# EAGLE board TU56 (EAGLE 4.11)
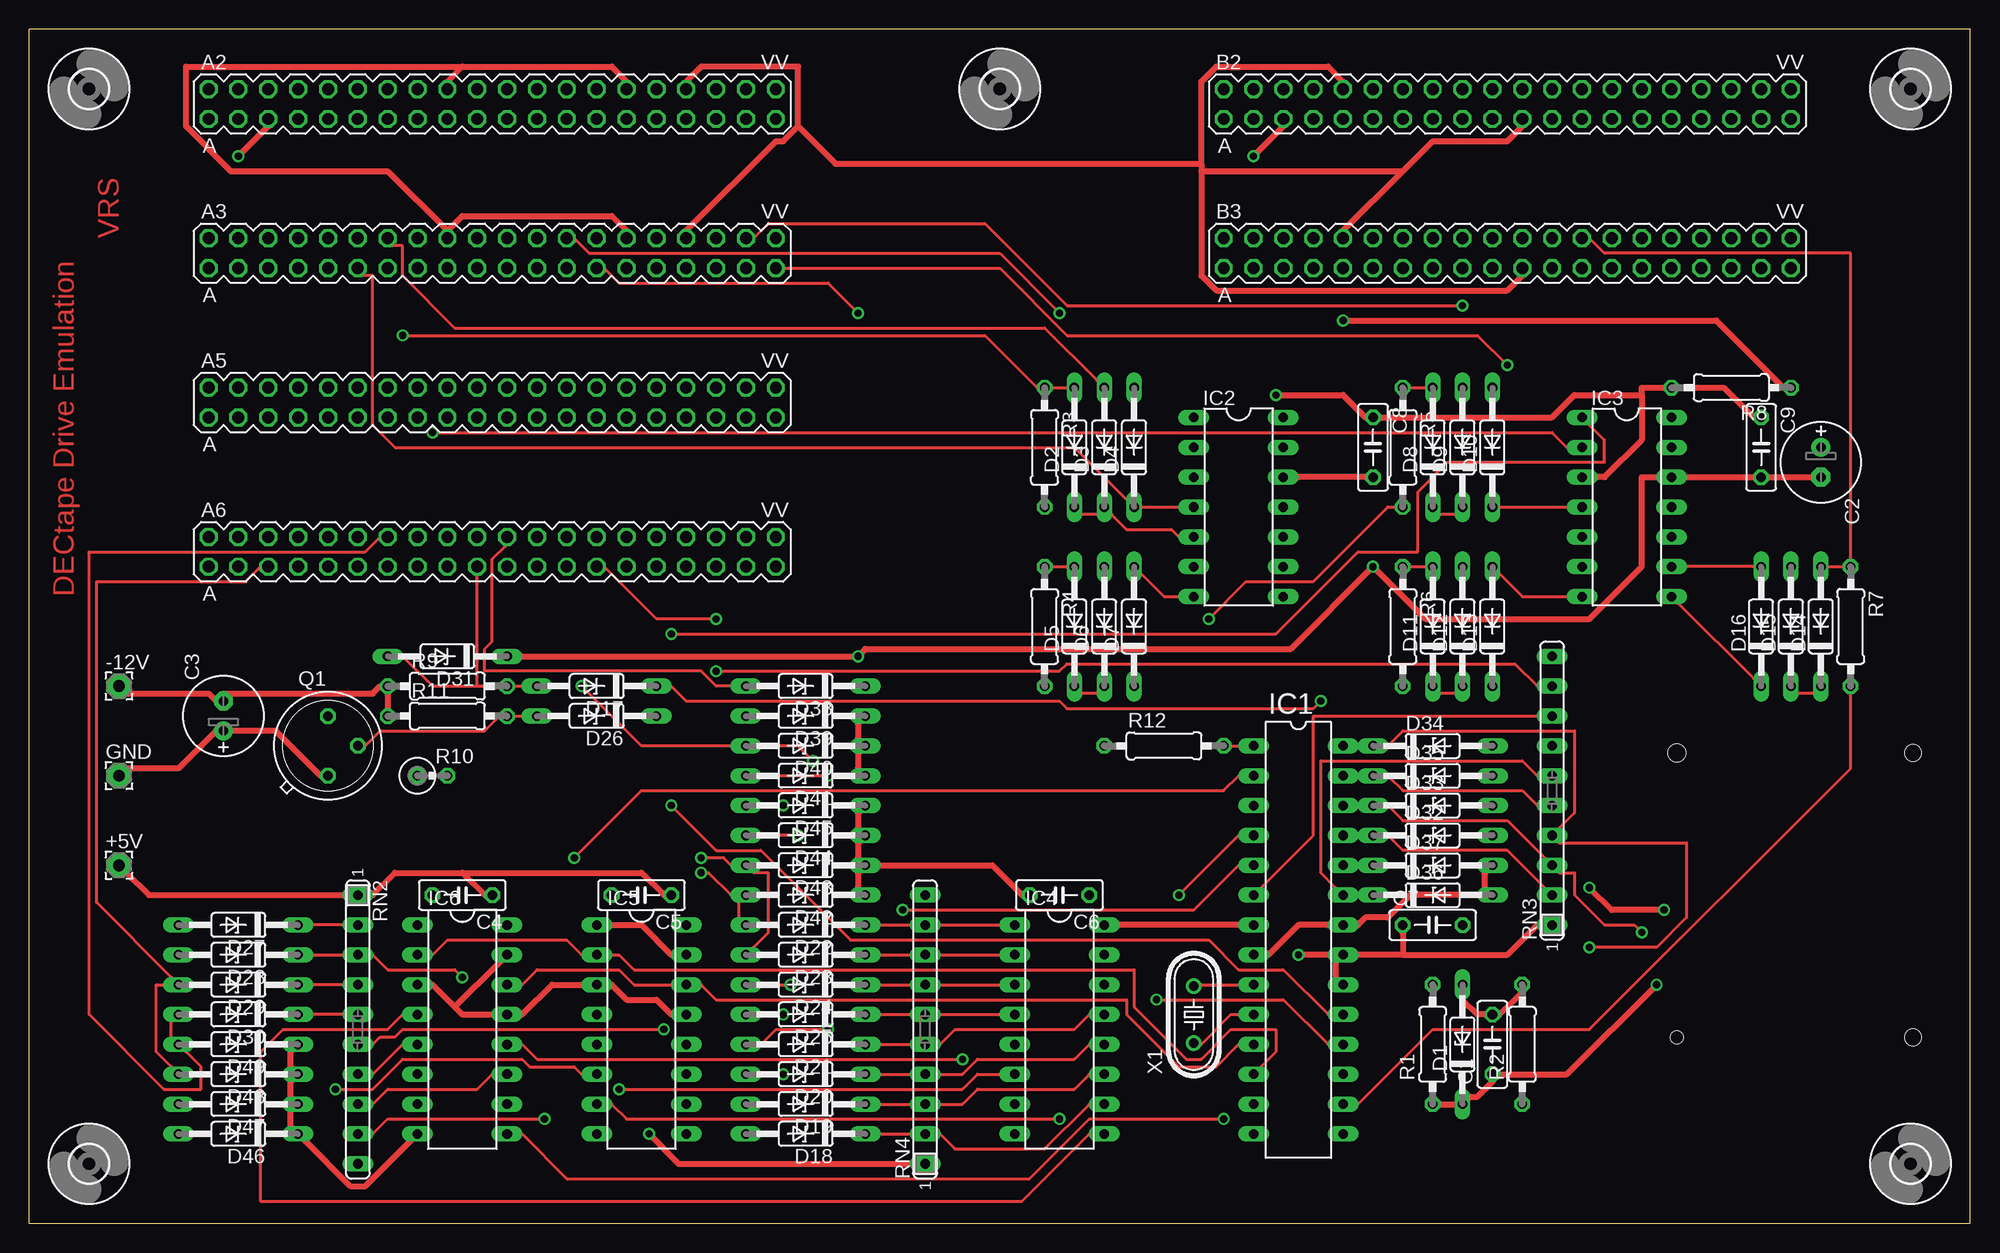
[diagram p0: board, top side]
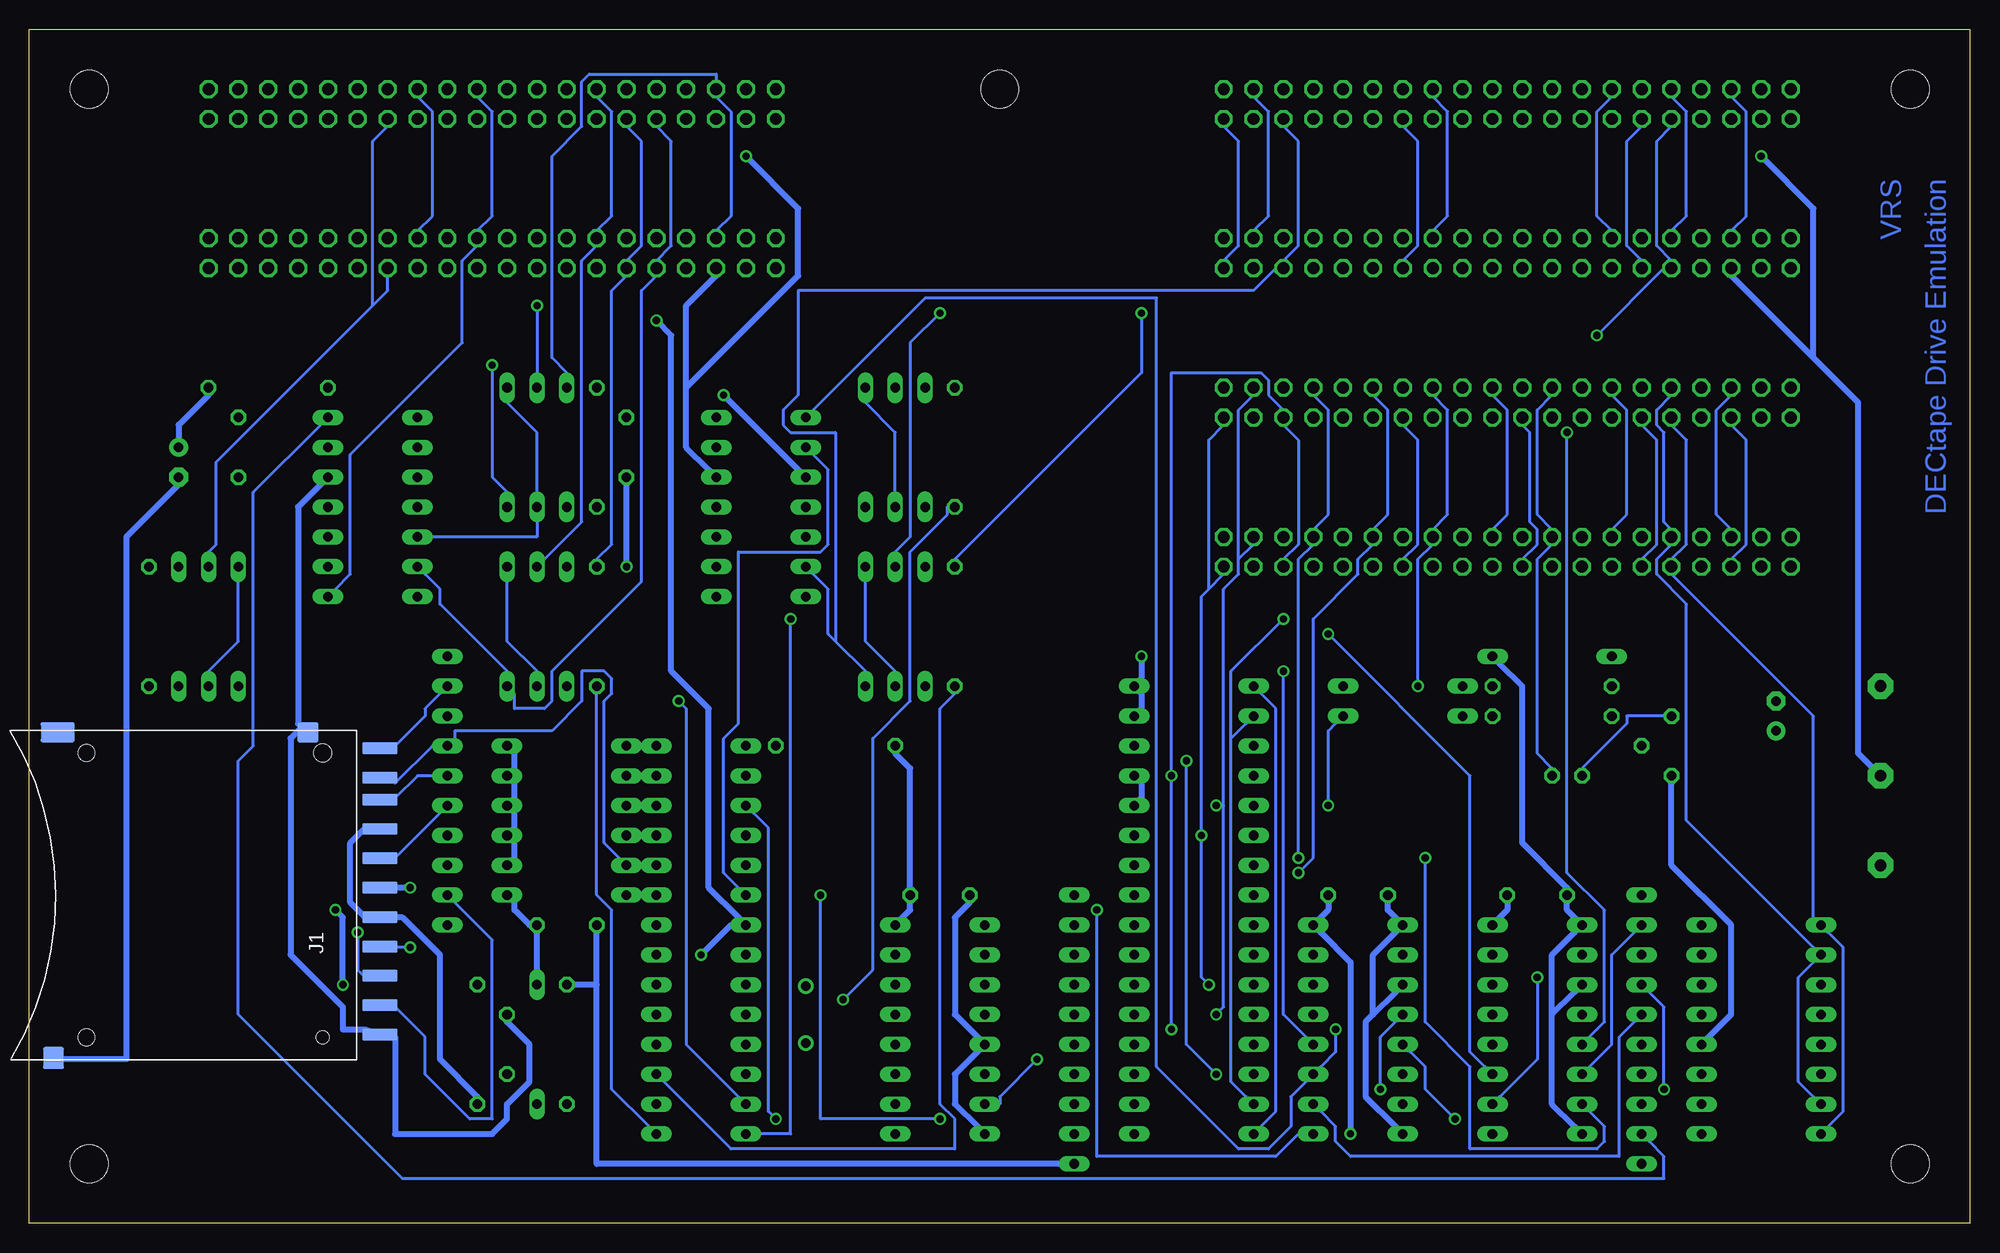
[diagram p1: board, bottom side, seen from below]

Size 165.1 x 101.6 mm. Coordinates in mm from the lower left corner, seen from the top.
Outline: 0,0 165.1,0 165.1,101.6 0,101.6 0,0
Copper layers (1*16): Top 0.035mm / dielectric 1.5mm / Bottom 0.035mm
Design rules "custompcb": minimum track width 10mil, minimum drill 24mil, track to track 8mil, track to pad 8mil, pad to pad 8mil, via to via 8mil, smd to smd 0mil, copper to edge 10mil, drill to drill 8mil, minimum pad ring 10mil, minimum via ring 8mil, stop-mask expansion 4mil, vias tented up to drill 0mil, thermal gap 10mil
Net classes: 1 Supply: width 0.508 mm, drill 0.381 mm

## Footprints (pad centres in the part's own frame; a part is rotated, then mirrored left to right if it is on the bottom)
2,15/1,0 = drill 1.016 pad 2.159 octagon: 1 0,0
DEC40PINV = drill 1.016 octagon: A -24.13,-1.27; AA 3.81,-1.27; B -24.13,1.27; BB 3.81,1.27; C -21.59,-1.27; CC 6.35,-1.27; D -21.59,1.27; DD 6.35,1.27; E -19.05,-1.27; EE 8.89,-1.27; F -19.05,1.27; FF 8.89,1.27; H -16.51,-1.27; HH 11.43,-1.27; J -16.51,1.27; JJ 11.43,1.27; K -13.97,-1.27; KK 13.97,-1.27; L -13.97,1.27; LL 13.97,1.27; M -11.43,-1.27; MM 16.51,-1.27; N -11.43,1.27; NN 16.51,1.27; P -8.89,-1.27; PP 19.05,-1.27; R -8.89,1.27; RR 19.05,1.27; S -6.35,-1.27; SS 21.59,-1.27; T -6.35,1.27; TT 21.59,1.27; U -3.81,-1.27; UU 24.13,-1.27; V -3.81,1.27; VV 24.13,1.27; W -1.27,-1.27; X -1.27,1.27; Y 1.27,-1.27; Z 1.27,1.27
C050-025X075 = drill 0.813 octagon: 1 -2.54,0; 2 2.54,0
E2,5-7 = drill 0.813 pad 1.6 round: + -1.27,0 | drill 0.813 pad 1.6 octagon: - 1.27,0
DO35Z10 = drill 0.813 long: A 5.08,0; C -5.08,0
DO35-10 = drill 0.813 long: A 5.08,0; C -5.08,0
DIL28-3 = drill 0.813 long: 1 -16.51,-3.81; 2 -13.97,-3.81; 3 -11.43,-3.81; 4 -8.89,-3.81; 5 -6.35,-3.81; 6 -3.81,-3.81; 7 -1.27,-3.81; 8 1.27,-3.81; 9 3.81,-3.81; 10 6.35,-3.81; 11 8.89,-3.81; 12 11.43,-3.81; 13 13.97,-3.81; 14 16.51,-3.81; 15 16.51,3.81; 16 13.97,3.81; 17 11.43,3.81; 18 8.89,3.81; 19 6.35,3.81; 20 3.81,3.81; 21 1.27,3.81; 22 -1.27,3.81; 23 -3.81,3.81; 24 -6.35,3.81; 25 -8.89,3.81; 26 -11.43,3.81; 27 -13.97,3.81; 28 -16.51,3.81
DIL14 = drill 0.813 long: 1 -7.62,-3.81; 2 -5.08,-3.81; 3 -2.54,-3.81; 4 0,-3.81; 5 2.54,-3.81; 6 5.08,-3.81; 7 7.62,-3.81; 8 7.62,3.81; 9 5.08,3.81; 10 2.54,3.81; 11 0,3.81; 12 -2.54,3.81; 13 -5.08,3.81; 14 -7.62,3.81
DIL16 = drill 0.813 long: 1 -8.89,-3.81; 2 -6.35,-3.81; 3 -3.81,-3.81; 4 -1.27,-3.81; 5 1.27,-3.81; 6 3.81,-3.81; 7 6.35,-3.81; 8 8.89,-3.81; 9 8.89,3.81; 10 6.35,3.81; 11 3.81,3.81; 12 1.27,3.81; 13 -1.27,3.81; 14 -3.81,3.81; 15 -6.35,3.81; 16 -8.89,3.81
SCDA1A = smd 1 x 2.95: 1 -6.865,-10.76; 2 -4.365,-10.76; 3 -1.865,-10.76; 4 0.635,-10.76; 5 3.135,-10.76; 6 5.635,-10.76; 7 8.135,-10.76; 8 10,-10.76; 9 -9.365,-10.76; 10 12.5,-10.76; 13 -11.865,-10.76 | smd 1.7 x 1.8: 11 13.85,-4.65 | smd 1.7 x 2.9: 12 13.85,16.65 | smd 1.9 x 1.8: 14 -13.85,17 | hole 1.05: -12.1,-5.9 | hole 1.5: 12.1,-5.9 | hole 1.4: 12.1,14.2; -12.1,14.2
TO5 = drill 0.813 octagon: 1 0,-2.54; 2 2.54,0; 3 0,2.54
0207/10 = drill 0.813 octagon: 1 -5.08,0; 2 5.08,0
0309V = drill 0.813 octagon: 1 -1.27,0; 2 1.27,0
SIL10 = drill 0.813 long: 1 -11.43,0; 2 -8.89,0; 3 -6.35,0; 4 -3.81,0; 5 -1.27,0; 6 1.27,0; 7 3.81,0; 8 6.35,0; 9 8.89,0; 10 11.43,0
3,2 = hole 3.2: 0,0
HC49/S = drill 0.813 round: 1 -2.413,0; 2 2.413,0

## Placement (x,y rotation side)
+5V  [2,15/1,0]  7.62,30.48 0 top
-12V  [2,15/1,0]  7.62,45.72 0 top
A2  [DEC40PINV]  39.37,95.25 0 top
A3  [DEC40PINV]  39.37,82.55 0 top
A5  [DEC40PINV]  39.37,69.85 0 top
A6  [DEC40PINV]  39.37,57.15 0 top
B2  [DEC40PINV]  125.73,95.25 0 top
B3  [DEC40PINV]  125.73,82.55 0 top
C1  .01  [C050-025X075]  124.46,15.24 90 top
C2  10uf  [E2,5-7]  152.4,64.77 270 top
C3  10uf  [E2,5-7]  16.51,43.18 90 top
C4  .01  [C050-025X075]  36.83,27.94 180 top
C5  .01  [C050-025X075]  52.07,27.94 180 top
C6  .01  [C050-025X075]  87.63,27.94 180 top
C7  .01  [C050-025X075]  119.38,25.4 0 top
C8  .01  [C050-025X075]  114.3,66.04 270 top
C9  .01  [C050-025X075]  147.32,66.04 270 top
D1  3.3V  [DO35Z10]  121.92,15.24 90 top
D2  1N4148  [DO35-10]  88.9,66.04 90 top
D3  1N4148  [DO35-10]  91.44,66.04 90 top
D4  1N4148  [DO35-10]  93.98,66.04 90 top
D5  1N4148  [DO35-10]  88.9,50.8 90 top
D6  1N4148  [DO35-10]  91.44,50.8 90 top
D7  1N4148  [DO35-10]  93.98,50.8 90 top
D8  1N4148  [DO35-10]  119.38,66.04 90 top
D9  1N4148  [DO35-10]  121.92,66.04 90 top
D10  1N4148  [DO35-10]  124.46,66.04 90 top
D11  1N4148  [DO35-10]  119.38,50.8 90 top
D12  1N4148  [DO35-10]  121.92,50.8 90 top
D13  1N4148  [DO35-10]  124.46,50.8 90 top
D14  1N4148  [DO35-10]  152.4,50.8 90 top
D15  1N4148  [DO35-10]  149.86,50.8 90 top
D16  1N4148  [DO35-10]  147.32,50.8 90 top
D17  3.3V  [DO35Z10]  48.26,45.72 180 top
D18  3.3V  [DO35Z10]  66.04,7.62 180 top
D19  3.3V  [DO35Z10]  66.04,10.16 180 top
D20  3.3V  [DO35Z10]  66.04,12.7 180 top
D21  3.3V  [DO35Z10]  66.04,15.24 180 top
D22  3.3V  [DO35Z10]  66.04,25.4 180 top
D23  3.3V  [DO35Z10]  66.04,22.86 180 top
D24  3.3V  [DO35Z10]  66.04,20.32 180 top
D25  3.3V  [DO35Z10]  66.04,17.78 180 top
D26  3.3V  [DO35Z10]  48.26,43.18 180 top
D27  3.3V  [DO35Z10]  17.78,25.4 180 top
D28  3.3V  [DO35Z10]  17.78,22.86 180 top
D29  3.3V  [DO35Z10]  17.78,20.32 180 top
D30  3.3V  [DO35Z10]  17.78,17.78 180 top
D31  3.3V  [DO35Z10]  35.56,48.26 180 top
D32  3.3V  [DO35Z10]  119.38,33.02 0 top
D33  3.3V  [DO35Z10]  119.38,35.56 0 top
D34  3.3V  [DO35Z10]  119.38,40.64 0 top
D35  3.3V  [DO35Z10]  119.38,38.1 0 top
D36  3.3V  [DO35Z10]  119.38,27.94 0 top
D37  3.3V  [DO35Z10]  119.38,30.48 0 top
D38  3.3V  [DO35Z10]  66.04,45.72 180 top
D39  3.3V  [DO35Z10]  66.04,43.18 180 top
D40  3.3V  [DO35Z10]  66.04,40.64 180 top
D41  3.3V  [DO35Z10]  66.04,38.1 180 top
D42  3.3V  [DO35Z10]  66.04,27.94 180 top
D43  3.3V  [DO35Z10]  66.04,30.48 180 top
D44  3.3V  [DO35Z10]  66.04,33.02 180 top
D45  3.3V  [DO35Z10]  66.04,35.56 180 top
D46  3.3V  [DO35Z10]  17.78,7.62 180 top
D47  3.3V  [DO35Z10]  17.78,10.16 180 top
D48  3.3V  [DO35Z10]  17.78,12.7 180 top
D49  3.3V  [DO35Z10]  17.78,15.24 180 top
GND  [2,15/1,0]  7.62,38.1 0 top
IC1  ATMEGA8L-8P  [DIL28-3]  107.95,24.13 270 top
IC2  LM339N  [DIL14]  102.87,60.96 270 top
IC3  LM339N  [DIL14]  135.89,60.96 270 top
IC4  74LS148N  [DIL16]  87.63,16.51 270 top
IC5  74LS153N  [DIL16]  52.07,16.51 270 top
IC6  74LS153N  [DIL16]  36.83,16.51 270 top
J1  SDCARDMOUSER  [SCDA1A]  146.05,27.94 90 bottom
Q1  2N2905  [TO5]  25.4,40.64 0 top
R1  [0207/10]  119.38,15.24 90 top
R2  0  [0207/10]  127,15.24 90 top
R3  10K  [0207/10]  86.36,66.04 270 top
R4  10K  [0207/10]  86.36,50.8 270 top
R5  10K  [0207/10]  116.84,66.04 270 top
R6  10K  [0207/10]  116.84,50.8 270 top
R7  10K  [0207/10]  154.94,50.8 270 top
R8  0  [0207/10]  144.78,71.12 180 top
R9  10K  [0207/10]  35.56,45.72 0 top
R10  100 1/2W  [0309V]  34.29,38.1 0 top
R11  10K  [0207/10]  35.56,43.18 0 top
R12  0  [0207/10]  96.52,40.64 0 top
RN2  [SIL10]  27.94,16.51 270 top
RN3  [SIL10]  129.54,36.83 90 top
RN4  [SIL10]  76.2,16.51 90 top
U$1  [3,2]  5.08,5.08 0 top
U$2  [3,2]  5.08,96.52 0 top
U$3  [3,2]  160.02,96.52 0 top
U$4  [3,2]  160.02,5.08 0 top
U$5  [3,2]  82.55,96.52 0 top
X1  [HC49/S]  99.06,17.78 90 top

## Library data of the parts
+5V -12V GND = wirepad
A2 A3 A5 A6 B2 B3 = dec-con
C1-C9 R1-R12 = rcl
D1-D49 = diode
IC1 = avr
IC2 IC3 = linear
IC4-IC6 = 74xx-jameco
J1 = sdcards
Q1 = transistor-pnp
RN2-RN4 = resistor-sil
U$1-U$5 = holes
X1 = crystal

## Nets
-12V [Supply]: -12V.1 C3.- R9.1 R11.1
A: IC1.11 IC5.14 IC6.14
B: IC1.12 IC5.2 IC6.2
CD\: IC5.12 J1.10 RN3.9
CLK: D35.C IC1.27 J1.5 RN3.5
CMD: D34.C IC1.28 J1.2 RN3.4
D0: IC1.5 IC5.9
D1: IC1.4 IC5.7
D1IN: IC3.14 IC5.5 RN2.9
D1OUT: IC1.16 R7.2
D2: IC1.3 IC6.9
D2IN: IC3.1 IC6.11 RN2.8
D2OUT: IC1.15 R6.2
D3: IC1.2 IC6.7
D3IN: IC3.2 IC6.5 RN2.7
D3OUT: IC1.14 R5.2
DAT0: D36.C IC1.23 J1.7 RN3.6
DAT1: D37.C IC1.24 J1.8 RN3.7
DAT2: D32.C IC1.25 J1.9 RN3.2
DAT3: D33.C IC1.26 J1.1 RN3.3
DATA1+: B2.DD B3.DD D14.A R7.1
DATA1-: B2.EE B3.EE D15.A
DATA1CT: B2.Z B3.Z D16.C IC3.8
DATA2+: B2.M B3.M D11.A R6.1
DATA2-: B2.R B3.R D12.A
DATA2CT: B2.K B3.K D13.C IC3.6
DATA3+: B2.F B3.F D8.A R5.1
DATA3-: A2.TT A3.TT D9.A
DATA3CT: A2.UU A3.UU D10.C IC3.4
DRV0: IC4.6 IC5.4
DRV1: IC4.7 IC6.12
DRV2: IC4.9 IC6.4
DRVOK: D26.C IC1.19
FORWARD: D27.C IC6.6 RN2.2
FORWARD\: A5.K A6.K D27.A D46.A
GND [Supply]: A2.E A3.E B2.E B3.E C1.2 C2.- C3.+ C4.2 C5.2 C6.2 C7.2 C8.2 C9.2 D1.A D31.C D32.A D33.A D34.A D35.A D36.A D37.A D38.C D39.C D40.C D41.C D42.C D43.C D44.C D45.C D46.C D47.C D48.C D49.C GND.1 IC1.8 IC1.22 IC2.12 IC3.12 IC4.5 IC4.8 IC5.1 IC5.3 IC5.8 IC5.13 IC5.15 IC6.1 IC6.3 IC6.8 IC6.13 IC6.15 J1.11 J1.13 J1.14 Q1.1 R2.2
GO\: A5.F A6.F
HALT: D30.C IC5.10 RN2.5
HALT\: A5.R A6.R D30.A D49.A
J: A5.M A6.M
MARK+: A2.EE A3.EE D5.A R4.1
MARK-: A2.DD A3.DD D6.A
MARKCT: A2.PP A3.PP D7.C IC2.6
MIN: IC2.1 IC5.11 RN2.6
MOUT: IC1.17 R4.2
N$1: IC1.10 X1.1
N$2: IC1.9 X1.2
N$3: D18.C IC4.10 RN4.2
N$4: D19.C IC4.11 RN4.3
N$5: D20.C IC4.12 RN4.4
N$7: D2.C D3.C D4.A IC2.5
N$8: D21.C IC4.13 RN4.5
N$9: D22.C IC4.1 RN4.9
N$10: D23.C IC4.2 RN4.8
N$11: D5.C D6.C D7.A IC2.7
N$12: D8.C D9.C D10.A IC3.5
N$13: D11.C D12.C D13.A IC3.7
N$14: D14.C D15.C D16.A IC3.9
N$15: D24.C IC4.3 RN4.7
N$16: D25.C IC4.4 RN4.6
N$17: IC1.1 R12.2
N$18: Q1.3 R10.1
N$19: D26.A Q1.2 R11.2
REVERSE: D28.C IC6.10 RN2.3
REVERSE\: A5.L A6.L D28.A D47.A
SELECT: A5.V A6.V R10.2
SELECT0\: A5.Z A6.Z D18.A D38.A
SELECT1\: A5.EE A6.EE D19.A D39.A
SELECT2\: A5.DD A6.DD D20.A D40.A
SELECT3\: A5.PP A6.PP D21.A D41.A
SELECT4\: A5.JJ A6.JJ D22.A D42.A
SELECT5\: A5.NN A6.NN D23.A D43.A
SELECT6\: A5.UU A6.UU D24.A D44.A
SELECT7\: A5.TT A6.TT D25.A D45.A
SELECT\: A2.L A3.L
SHIELD1 [Supply]: A2.JJ A2.V A3.JJ A3.V
SHIELD2 [Supply]: A2.NN A3.NN B2.L B2.Y B3.L B3.Y
SKEW: A2.F A3.F
STOP: D29.C IC5.6 RN2.4
STOP\: A5.E A6.E D29.A D48.A
TIMING+: A2.K A3.K D2.A R3.1
TIMING-: A2.R A3.R D3.A
TIMINGCT: A2.M A3.M D4.C IC2.4
TIN: IC1.6 IC2.2 RN3.8
TOUT: IC1.18 R3.2
V+ [Supply]: C8.1 C9.1 IC2.3 IC3.3 R8.2
VCC [Supply]: +5V.1 C2.+ C4.1 C5.1 C6.1 C7.1 IC1.7 IC1.20 IC1.21 IC4.16 IC5.16 IC6.16 R1.2 R8.1 R12.1 RN2.1 RN3.1 RN4.1
VDD [Supply]: C1.1 D1.C J1.4 R1.1
VSS [Supply]: J1.3 J1.6 R2.1
WE: A5.W A6.W D17.A D31.A R9.2
WE\: D17.C IC1.13

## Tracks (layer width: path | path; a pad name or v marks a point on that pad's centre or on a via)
-12V
  Top 0.508: R11.1 30.48,43.81 30.48,45.09 R9.1 29.84,45.72 29.21,45.09 16.51,45.09 C3.- 15.88,44.45 15.24,45.09 8.26,45.09 -12V.1
A
  Top 0.254: IC6.14 41.91,20.32 43.18,21.59 50.16,21.59 51.44,20.32 54.61,20.32 IC5.14 57.15,20.32 58.42,19.05 93.34,19.05 93.34,17.78 97.79,13.34 100.97,13.34 102.87,15.24 IC1.11
B
  Top 0.254: IC6.2 34.29,22.86 35.56,24.13 45.72,24.13 46.99,22.86 IC5.2 49.53,22.86 50.16,22.86 51.44,21.59 93.98,21.59 93.98,18.41 98.42,13.97 99.69,13.97 102.23,16.51 106.05,16.51 106.05,14.61 104.78,13.34 IC1.12
CD\  (via drill 0.61)
  Top 0.254: v58.42,46.99 87.63,46.99 88.27,47.62 126.36,47.62 128.27,45.72 RN3.9
  Bottom 0.254: v58.42,46.99 58.42,17.78 56.52,15.88 IC5.12 | J1.10 133.99,40.64 131.44,43.18 131.44,43.81 130.18,45.09 RN3.9
CLK
  Top 0.254: IC1.27 113.03,38.1 D35.C 115.57,38.1 116.84,36.83 127,36.83 128.27,35.56 RN3.5
  Bottom 0.254: RN3.5 130.18,34.92 133.99,31.11 J1.5
CMD  (via drill 0.61)
  Top 0.254: IC1.28 113.03,40.64 D34.C 115.57,40.64 116.84,41.91 131.44,41.91 131.44,34.92 130.18,33.66 RN3.4 130.18,32.38 140.97,32.38 140.97,26.04 138.43,23.5 v132.72,23.5
  Bottom 0.254: v132.72,23.5 133.99,23.5 J1.2
D0  (via drill 0.61)
  Top 0.254: v74.3,26.67 99.06,26.67 102.87,30.48 IC1.5
  Bottom 0.254: v74.3,26.67 74.3,5.71 59.05,5.71 57.15,7.62 IC5.9
D1  (via drill 0.61)
  Top 0.254: v87.63,8.89 50.8,8.89 49.53,10.16 IC5.7 | v97.79,27.94 102.87,33.02 IC1.4
  Bottom 0.254: v87.63,8.89 97.79,8.89 v97.79,27.94
D1IN  (via drill 0.61)
  Top 0.254: v43.81,8.89 30.48,8.89 29.21,7.62 RN2.9
  Bottom 0.254: v43.81,8.89 46.35,11.43 46.35,13.34 47.62,14.61 IC5.5 | IC3.14 140.34,67.94 146.05,62.23 146.05,40.64 147.32,39.37 147.32,17.78 133.35,3.81 26.04,3.81 26.04,5.71 27.3,6.99 RN2.9
D1OUT
  Top 0.254: IC1.16 113.03,10.16 119.38,16.51 132.72,16.51 154.94,38.73 154.94,45.09 R7.2
D2  (via drill 0.61)
  Top 0.254: v101.6,8.89 90.17,8.89 85.09,3.81 45.72,3.81 41.91,7.62 IC6.9
  Bottom 0.254: v101.6,8.89 102.23,9.53 102.23,33.66 103.5,34.92 IC1.3
D2IN  (via drill 0.61)
  Top 0.254: RN2.8 29.21,10.16 30.48,11.43 38.1,11.43 39.37,12.7 IC6.11 | v54.61,50.16 106.05,50.16 113.03,57.15 118.11,57.15 118.11,62.23 120.65,64.77 133.99,64.77 133.99,66.67 132.72,67.94 IC3.1
  Bottom 0.254: v54.61,50.16 42.55,38.1 42.55,14.61 41.27,13.34 IC6.11
D2OUT
  Bottom 0.254: IC1.15 112.39,8.26 115.57,11.43 115.57,26.67 116.84,27.94 116.84,45.09 R6.2
D3  (via drill 0.61)
  Top 0.254: v46.35,31.11 52.07,36.83 101.6,36.83 102.87,38.1 IC1.2
  Bottom 0.254: v46.35,31.11 46.35,17.14 42.55,13.34 42.55,6.35 31.75,6.35 31.11,6.99 31.11,8.26 32.38,9.53 IC6.7
D3IN  (via drill 0.61)
  Top 0.254: RN2.7 29.21,12.7 31.75,15.24 IC6.5 | v34.29,67.31 129.54,67.31 130.81,66.04 IC3.2
  Bottom 0.254: v34.29,67.31 34.29,29.84 31.11,26.67 31.11,17.14 32.38,15.88 IC6.5
D3OUT  (via drill 0.61)
  Top 0.254: v100.33,51.44 103.5,54.61 109.22,54.61 115.57,60.96 116.2,60.96 R5.2
  Bottom 0.254: v100.33,51.44 100.33,7.62 102.87,7.62 IC1.14
DAT0
  Top 0.254: D36.C 113.03,27.94 IC1.23 111.12,28.57 109.86,29.84 109.86,39.37 127,39.37 128.27,38.1 RN3.6
  Bottom 0.254: RN3.6 130.81,38.1 132.08,38.1 133.99,36.2 J1.7
DAT1
  Top 0.254: IC1.24 113.03,30.48 D37.C
  Bottom 0.254: J1.8 133.99,37.47 130.81,40.64 RN3.7 128.91,41.27 128.91,41.91 120.65,41.91 118.11,44.45 118.11,46.99 116.2,46.99 115.57,46.35 115.57,45.09 116.2,44.45 116.2,32.38 114.94,31.11 D37.C
DAT2
  Top 0.254: IC1.25 113.03,33.02 D32.C 115.57,33.02 116.84,31.75 125.73,31.75 128.91,28.57 RN3.2
  Bottom 0.254: J1.9 133.99,18.41 131.44,15.88 131.44,12.7 127.64,8.89 125.73,8.89 125.73,24.13 128.91,27.3 RN3.2
DAT3  (via drill 0.61)
  Top 0.254: IC1.26 113.03,35.56 D33.C 115.57,35.56 116.84,34.29 125.73,34.29 128.91,31.11 RN3.3 130.18,29.84 131.44,29.84 131.44,27.94 133.99,25.4 136.53,25.4 v137.16,24.77
  Bottom 0.254: v137.16,24.77 137.16,21.59 136.53,20.95 J1.1
DATA1+
  Top 0.254: D14.A 153.03,55.88 154.31,55.88 R7.1 154.94,56.52 154.94,82.55 133.99,82.55 132.72,83.82 B3.DD
  Bottom 0.254: B3.DD 132.08,84.45 130.81,85.72 130.81,94.61 132.08,95.89 B2.DD
DATA1-
  Bottom 0.254: 135.89,78.11 134.62,79.38 134.62,80.64 B3.EE | 135.89,78.11 149.22,64.77 149.22,57.78 149.86,57.15 D15.A | 135.89,78.11 135.89,92.08 134.62,93.34 B2.EE
DATA1CT
  Top 0.254: IC3.8 140.34,52.7 146.69,46.35 D16.C
  Bottom 0.254: B2.Z 127,95.89 125.73,94.61 125.73,85.72 127,84.45 B3.Z 127,83.19 128.27,81.92 128.27,74.93 137.79,65.41 137.79,55.24 139.06,53.98 IC3.8
DATA2+
  Top 0.254: R6.1 117.47,55.88 118.75,55.88 D11.A
  Bottom 0.254: B2.M 114.3,93.34 113.03,92.08 113.03,83.19 114.3,81.92 B3.M 114.3,80.64 115.57,79.38 115.57,57.78 116.84,56.52 R6.1
DATA2-
  Bottom 0.254: D12.A 121.28,56.52 118.11,59.69 118.11,81.92 116.84,83.19 B3.R 116.84,84.45 115.57,85.72 115.57,94.61 116.84,95.89 B2.R
DATA2CT
  Bottom 0.254: B2.K 111.76,93.34 110.49,92.08 110.49,83.19 111.76,81.92 B3.K 111.76,80.64 113.03,79.38 113.03,54.61 120.65,46.99 120.65,44.45 121.28,43.81 123.83,43.81 123.83,45.09 D13.C 124.46,46.99 130.18,52.7 130.18,53.98 131.44,55.24 IC3.6
DATA3+
  Top 0.254: R5.1 117.47,71.12 118.75,71.12 D8.A
  Bottom 0.254: B3.F 106.68,84.45 105.41,85.72 105.41,94.61 106.68,95.89 B2.F 106.68,97.16 106.68,97.79 117.47,97.79 118.11,97.16 118.11,93.34 120.65,90.81 120.65,73.66 119.38,72.39 D8.A
DATA3-  (via drill 0.61)
  Top 0.254: v121.92,78.11 88.27,78.11 81.28,85.09 62.87,85.09 61.59,83.82 A3.TT
  Bottom 0.254: A3.TT 60.96,84.45 59.69,85.72 59.69,94.61 60.96,95.89 A2.TT | v121.92,78.11 121.92,72.39 D9.A
DATA3CT  (via drill 0.61)
  Top 0.254: D10.C 125.09,60.96 130.81,60.96 IC3.4 | v125.73,73.03 123.19,75.56 88.27,75.56 82.55,81.28 64.14,81.28 A3.UU
  Bottom 0.254: A3.UU 63.5,81.92 62.23,83.19 62.23,92.08 63.5,93.34 A2.UU | v125.73,73.03 125.73,63.5 124.46,62.23 D10.C
DRV0  (via drill 0.61)
  Top 0.254: v50.16,11.43 79.38,11.43 80.64,12.7 82.55,12.7 IC4.6
  Bottom 0.254: v50.16,11.43 50.16,15.88 48.9,17.14 IC5.4
DRV1  (via drill 0.61)
  Top 0.254: v79.38,13.97 43.18,13.97 41.91,15.24 IC6.12
  Bottom 0.254: v79.38,13.97 82.55,10.79 82.55,10.16 IC4.7
DRV2
  Top 0.254: IC6.4 31.75,17.78 30.48,16.51 21.59,16.51 19.68,14.61 19.68,1.91 84.45,1.91 90.17,7.62 IC4.9
DRVOK  (via drill 0.61)
  Top 0.254: v54.61,35.56 58.42,31.75 62.23,31.75 69.85,24.13 100.33,24.13 102.87,21.59 106.68,21.59 110.49,17.78 IC1.19
  Bottom 0.254: v54.61,35.56 54.61,41.91 53.98,42.55 D26.C
FORWARD
  Top 0.254: D27.C 24.13,25.4 26.67,25.4 RN2.2
  Bottom 0.254: IC6.6 32.38,13.34 30.48,15.24 30.48,22.86 28.57,24.77 RN2.2
FORWARD\
  Bottom 0.254: A5.K 25.4,67.94 24.13,66.67 24.13,57.78 25.4,56.52 A6.K 25.4,55.24 13.34,43.18 13.34,26.04 D27.A 12.06,24.77 10.79,23.5 10.79,9.53 12.06,8.26 D46.A
GND  (via drill 0.61)
  Top 0.508: C2.- 151.76,63.5 147.96,63.5 C9.2 146.69,63.5 140.97,63.5 IC3.12 138.43,63.5 137.16,63.5 137.16,55.88 132.72,51.44 118.75,51.44 v114.3,55.88 107.31,48.9 71.12,48.9 v70.48,48.26 41.91,48.26 D31.C | IC1.8 105.41,22.86 107.95,25.4 110.49,25.4 IC1.22 113.03,25.4 113.67,26.04 115.57,26.04 117.47,27.94 123.19,27.94 D36.A 123.83,28.57 123.83,29.84 D37.A | D1.A 121.92,19.05 123.19,17.78 123.83,17.78 C1.2 125.09,17.78 127,19.68 R2.2 | IC2.12 107.95,63.5 113.67,63.5 C8.2 | v104.14,90.81 106.68,93.34 B2.E | Q1.1 24.77,38.1 20.95,41.91 17.14,41.91 C3.+ 15.88,41.91 12.7,38.73 8.26,38.73 GND.1 | v17.78,90.81 20.32,93.34 A2.E | D42.C 70.48,28.57 70.48,29.84 D43.C | C6.2 84.45,27.94 81.92,30.48 72.39,30.48 D43.C | D43.C 70.48,31.11 70.48,32.38 D44.C 70.48,33.66 70.48,34.92 D45.C | D41.C 70.48,38.73 70.48,40.01 D40.C 70.48,41.27 70.48,42.55 D39.C | IC6.8 32.38,6.99 28.57,3.17 27.3,3.17 23.5,6.99 D46.C 22.23,8.26 22.23,9.53 D47.C 22.23,10.79 22.23,12.06 D48.C 22.23,13.34 22.23,14.61 D49.C | IC5.15 54.61,22.86 52.07,25.4 49.53,25.4 IC5.1 | IC5.13 54.61,17.78 53.34,19.05 50.8,19.05 49.53,20.32 IC5.3 46.99,20.32 44.45,20.32 41.91,17.78 IC6.13 39.37,17.78 36.83,17.78 36.2,18.41 | 36.2,18.41 34.29,20.32 IC6.3 | 36.2,18.41 40.01,22.23 IC6.15
  Bottom 0.508: J1.14 162.56,13.97 156.84,13.97 156.84,58.42 152.4,62.87 C2.- | D36.A 123.83,27.3 123.83,26.67 122.56,25.4 C7.2 121.92,24.77 121.92,21.59 D1.A | D37.A 123.83,31.11 123.83,32.38 D32.A 123.83,33.66 123.83,34.92 D33.A 123.83,36.2 123.83,37.47 D35.A 123.83,38.73 123.83,40.01 D34.A | 109.22,71.12 109.22,66.04 107.31,64.14 IC2.12 | 109.22,71.12 109.22,78.11 106.68,80.64 B3.E | v104.14,90.81 99.69,86.36 99.69,80.64 109.22,71.12 | IC3.12 140.34,62.87 142.24,60.96 142.24,42.55 J1.11 142.24,41.91 142.88,41.27 142.88,22.86 138.43,18.41 138.43,16.51 136.53,16.51 J1.13 133.99,15.88 133.99,7.62 125.73,7.62 124.46,8.89 124.46,10.16 122.56,12.06 122.56,15.24 124.46,17.14 C1.2 | v114.3,55.88 114.3,62.87 C8.2 | 13.34,73.66 9.53,69.85 9.53,40.01 8.26,38.73 GND.1 | 13.34,73.66 20.32,80.64 A3.E | v17.78,90.81 13.34,86.36 13.34,73.66 | IC4.8 84.45,8.26 86.36,10.16 86.36,12.7 84.45,14.61 IC4.5 84.45,15.88 86.36,17.78 86.36,26.04 85.09,27.3 C6.2 | D41.C 70.48,37.47 70.48,36.2 D45.C | D39.C 70.48,43.81 70.48,45.09 D38.C 70.48,46.35 v70.48,48.26 | D31.C 40.01,47.62 38.1,45.72 38.1,32.38 34.29,28.57 C4.2 34.29,27.3 34.29,26.67 33.66,26.04 IC6.1 33.66,24.77 35.56,22.86 35.56,17.78 | C5.2 49.53,27.3 49.53,26.67 48.9,26.04 IC5.1 48.9,24.77 50.8,22.86 50.8,17.78 | 50.8,17.78 48.9,19.68 IC5.3 | 50.8,17.78 51.44,17.14 51.44,10.79 48.9,8.26 IC5.8 | 35.56,17.78 35.56,10.16 33.66,8.26 IC6.8 | 35.56,17.78 33.66,19.68 IC6.3 | Q1.1 25.4,37.47 25.4,30.48 20.32,25.4 20.32,17.78 22.23,15.88 D49.C
GO\
  Bottom 0.254: A6.F 20.32,59.05 21.59,60.33 21.59,69.22 20.32,70.48 A5.F
HALT
  Top 0.254: D30.C 24.13,17.78 26.67,17.78 RN2.5
  Bottom 0.254: IC5.10 55.24,9.53 53.98,8.26 53.98,6.99 52.7,5.71 29.84,5.71 29.84,15.88 28.57,17.14 RN2.5
HALT\
  Top 0.254: D30.A 12.06,17.14 12.06,15.88 D49.A 13.34,14.61 14.61,13.34 14.61,11.43 11.43,11.43 5.08,17.78 5.08,57.15 28.57,57.15 29.84,58.42 A6.R
  Bottom 0.254: A6.R 30.48,59.05 29.21,60.33 29.21,69.22 30.48,70.48 A5.R
J
  Bottom 0.254: A6.M 27.94,56.52 26.67,57.78 26.67,66.67 27.94,67.94 A5.M
MARK+  (via drill 0.61)
  Top 0.254: R4.1 87,55.88 88.27,55.88 D5.A | v70.48,77.47 67.94,80.01 50.16,80.01 48.9,81.28 A3.EE
  Bottom 0.254: A3.EE 48.26,81.92 46.99,83.19 46.99,92.08 48.26,93.34 A2.EE | v70.48,77.47 70.48,72.39 86.36,56.52 R4.1
MARK-  (via drill 0.61)
  Top 0.254: v87.63,77.47 82.55,82.55 47.62,82.55 46.35,83.82 A3.DD
  Bottom 0.254: v87.63,77.47 90.17,74.93 90.17,58.42 91.44,57.15 D6.A | A2.DD 45.72,95.89 44.45,94.61 44.45,85.72 45.72,84.45 A3.DD
MARKCT
  Bottom 0.254: A2.PP 58.42,93.34 57.15,92.08 57.15,83.19 58.42,81.92 A3.PP 59.05,81.28 60.96,79.38 99.69,79.38 99.69,70.48 100.97,69.22 100.97,67.94 100.33,67.31 96.52,67.31 96.52,49.53 | 96.52,49.53 97.16,50.16 97.16,53.98 98.42,55.24 IC2.6 | 96.52,49.53 93.98,46.99 D7.C
MIN  (via drill 0.61)
  Top 0.254: v53.98,16.51 31.75,16.51 31.11,15.88 29.84,15.88 29.21,15.24 RN2.6
  Bottom 0.254: v53.98,16.51 53.98,14.61 55.24,13.34 IC5.11 56.52,12.06 57.78,10.79 57.78,8.26 59.69,6.35 62.23,6.35 69.22,13.34 69.22,78.74 88.9,78.74 98.42,69.22 IC2.1
MOUT
  Bottom 0.254: IC1.17 111.12,12.06 105.41,6.35 86.36,6.35 86.36,8.89 87.63,10.16 87.63,43.81 86.36,45.09 R4.2
N$1
  Top 0.254: X1.1 99.69,15.24 102.23,17.78 102.87,17.78 IC1.10
N$2
  Top 0.254: X1.2 99.69,20.32 102.87,20.32 IC1.9
N$3
  Top 0.254: D18.C 72.39,7.62 74.93,7.62 RN4.2 77.47,7.62 78.74,6.35 86.36,6.35 90.17,10.16 IC4.10
N$4
  Top 0.254: D19.C 72.39,10.16 74.93,10.16 RN4.3 77.47,10.16 79.38,10.16 80.64,11.43 88.9,11.43 90.17,12.7 IC4.11
N$5
  Top 0.254: D20.C 72.39,12.7 74.93,12.7 RN4.4 77.47,12.7 79.38,12.7 80.64,13.97 88.9,13.97 90.17,15.24 IC4.12
N$7
  Top 0.254: D2.C 89.53,60.33 90.81,60.33 D3.C 92.08,60.33 93.34,59.05 97.16,59.05 97.79,58.42 IC2.5
  Bottom 0.254: D4.A 93.98,69.85 91.44,67.31 91.44,62.23 D3.C
N$8
  Top 0.254: D21.C 72.39,15.24 74.93,15.24 RN4.5 77.47,15.24 78.74,16.51 88.9,16.51 90.17,17.78 IC4.13
N$9
  Top 0.254: D22.C 72.39,25.4 74.93,25.4 RN4.9 77.47,25.4 82.55,25.4 IC4.1
N$10
  Top 0.254: D23.C 72.39,22.86 74.93,22.86 RN4.8 77.47,22.86 82.55,22.86 IC4.2
N$11
  Top 0.254: D5.C 89.53,45.09 90.81,45.09 D6.C | D7.A 94.61,55.24 96.52,53.34 97.79,53.34 IC2.7
  Bottom 0.254: D6.C 91.44,46.99 93.98,49.53 93.98,54.61 D7.A
N$12
  Top 0.254: D8.C 120.02,60.33 121.28,60.33 D9.C
  Bottom 0.254: IC3.5 130.81,58.42 121.92,58.42 121.92,59.69 D9.C 121.92,62.23 121.92,67.31 124.46,69.85 D10.A
N$13
  Top 0.254: D11.C 120.02,45.09 121.28,45.09 D12.C | D13.A 125.09,55.24 127,53.34 130.81,53.34 IC3.7
  Bottom 0.254: D12.C 121.92,46.99 124.46,49.53 124.46,54.61 D13.A
N$14
  Top 0.254: D15.C 150.5,45.09 151.76,45.09 D14.C | IC3.9 140.97,55.88 146.69,55.88 D16.A
  Bottom 0.254: D15.C 149.86,46.99 147.32,49.53 147.32,54.61 D16.A
N$15
  Top 0.254: D24.C 72.39,20.32 74.93,20.32 RN4.7 77.47,20.32 82.55,20.32 IC4.3
N$16
  Top 0.254: D25.C 72.39,17.78 74.93,17.78 RN4.6 77.47,17.78 82.55,17.78 IC4.4
N$17
  Top 0.254: R12.2 102.23,40.64 102.87,40.64 IC1.1
N$18
  Bottom 0.254: Q1.3 26.04,43.18 29.21,43.18 29.21,42.55 33.02,38.73 R10.1
N$19
  Top 0.254: Q1.2 28.57,40.64 29.84,41.91 38.73,41.91 40.01,43.18 R11.2 41.27,43.18 41.91,43.18 D26.A
REVERSE  (via drill 0.61)
  Top 0.254: D28.C 24.13,22.86 26.67,22.86 RN2.3 29.21,22.86 30.48,21.59 36.2,21.59 v36.83,20.95
  Bottom 0.254: v36.83,20.95 36.83,13.97 40.01,10.79 IC6.10
REVERSE\
  Bottom 0.254: D47.A 13.34,10.79 14.61,12.06 14.61,20.95 13.34,22.23 D28.A 13.34,23.5 24.13,34.29 24.13,52.7 26.67,55.24 26.67,56.52 25.4,57.78 A6.L 25.4,59.05 26.04,59.69 26.04,67.31 26.67,67.94 26.67,69.22 25.4,70.48 A5.L
SELECT
  Bottom 0.254: R10.2 35.56,38.73 36.83,40.01 36.83,56.52 35.56,57.78 A6.V 35.56,59.05 36.83,60.33 36.83,69.22 35.56,70.48 A5.V
SELECT0\
  Top 0.254: A6.Z 40.64,57.78 39.37,56.52 39.37,49.53 38.73,48.9 38.73,46.99 57.15,46.99 58.42,45.72 59.69,45.72 D38.A
  Bottom 0.254: A6.Z 40.64,59.05 39.37,60.33 39.37,69.22 40.64,70.48 A5.Z | D18.A 60.33,8.26 59.05,9.53 59.05,43.81 60.33,45.09 D38.A
SELECT1\  (via drill 0.61)
  Top 0.254: v58.42,51.44 53.34,51.44 48.9,55.88 A6.EE
  Bottom 0.254: A6.EE 48.26,56.52 46.99,57.78 46.99,66.67 48.26,67.94 A5.EE | 62.87,41.27 62.87,12.06 61.59,10.79 D19.A | 62.87,41.27 61.59,42.55 D39.A | v58.42,51.44 62.87,46.99 62.87,41.27
SELECT2\  (via drill 0.61)
  Top 0.254: v64.14,12.7 62.23,12.7 D20.A | v66.67,39.37 65.41,40.64 62.23,40.64 D40.A 59.69,40.64 52.07,40.64 v46.99,45.72
  Bottom 0.254: A5.DD 45.72,70.48 44.45,69.22 44.45,60.33 45.72,59.05 A6.DD 45.72,57.78 46.99,56.52 v46.99,45.72 | v64.14,12.7 66.67,15.24 v66.67,39.37
SELECT3\  (via drill 0.61)
  Top 0.254: v67.94,16.51 63.5,16.51 62.23,15.24 D21.A | v67.94,38.1 62.23,38.1 D41.A
  Bottom 0.254: A6.PP 58.42,56.52 57.15,57.78 57.15,66.67 58.42,67.94 A5.PP 58.42,69.22 59.69,70.48 59.69,71.75 60.33,72.39 67.94,72.39 v67.94,38.1 v67.94,16.51
SELECT4\  (via drill 0.61)
  Top 0.254: D22.A 60.33,26.04 60.33,27.3 D42.A 59.69,27.94 57.78,29.84 v57.15,29.84
  Bottom 0.254: A5.JJ 50.8,70.48 49.53,69.22 49.53,60.33 50.8,59.05 A6.JJ 50.8,57.78 52.07,56.52 52.07,55.24 55.88,51.44 55.88,31.11 v57.15,29.84
SELECT5\  (via drill 0.61)
  Top 0.254: D23.A 61.59,23.5 62.87,24.77 62.87,29.84 61.59,29.84 D43.A 59.69,30.48 59.05,31.11 v57.15,31.11
  Bottom 0.254: A5.NN 55.88,70.48 54.61,69.22 54.61,60.33 55.88,59.05 A6.NN 55.88,57.78 57.15,56.52 v57.15,31.11
SELECT6\  (via drill 0.61)
  Top 0.254: v64.77,20.32 62.23,20.32 D24.A | v65.41,33.02 62.23,33.02 D44.A
  Bottom 0.254: v64.77,20.32 65.41,20.95 v65.41,33.02 65.41,53.34 64.77,53.98 | 64.77,53.98 63.5,55.24 A6.UU | 64.77,53.98 64.77,66.67 63.5,67.94 A5.UU
SELECT7\  (via drill 0.61)
  Top 0.254: v64.14,17.78 62.23,17.78 D25.A | v64.14,35.56 62.23,35.56 D45.A
  Bottom 0.254: v64.14,17.78 63.5,18.41 63.5,35.56 | 63.5,35.56 63.5,53.98 62.23,55.24 62.23,56.52 | 62.23,56.52 60.96,57.78 A6.TT | 63.5,35.56 v64.14,35.56 | 62.23,56.52 62.23,69.22 60.96,70.48 A5.TT
SELECT\
  Bottom 0.254: A3.L 25.4,84.45 24.13,85.72 24.13,94.61 25.4,95.89 A2.L
SHIELD1
  Top 0.508: 35.56,84.45 36.83,85.72 49.53,85.72 50.8,84.45 A3.JJ | 35.56,84.45 A3.V 35.56,84.45 | 36.83,98.42 35.56,97.16 A2.V | 36.83,98.42 49.53,98.42 50.8,97.16 A2.JJ | 35.56,84.45 30.48,89.53 17.14,89.53 13.34,93.34 13.34,98.42 36.83,98.42
SHIELD2
  Top 0.508: 65.41,93.34 64.14,92.08 63.5,92.08 55.88,84.45 A3.NN | 65.41,93.34 65.41,98.42 57.15,98.42 55.88,97.16 A2.NN | 116.84,89.53 119.38,92.08 125.73,92.08 127,93.34 B2.Y | 116.84,89.53 111.76,84.45 B3.L | 99.69,90.17 99.69,89.53 | 99.69,90.17 99.69,97.16 100.97,98.42 110.49,98.42 111.76,97.16 B2.L | 99.69,89.53 116.84,89.53 | 99.69,89.53 99.69,80.64 100.97,79.38 125.73,79.38 127,80.64 B3.Y | 65.41,93.34 68.58,90.17 99.69,90.17
SKEW
  Bottom 0.254: A3.F 20.32,84.45 19.05,85.72 19.05,94.61 20.32,95.89 A2.F
STOP  (via drill 0.61)
  Top 0.254: D29.C 24.13,20.32 26.67,20.32 RN2.4 | v26.04,11.43 29.21,11.43 31.75,13.97 41.91,13.97 42.55,13.34 46.35,13.34 46.99,12.7 IC5.6
  Bottom 0.254: v26.04,11.43 26.04,18.41 27.3,19.68 RN2.4
STOP\
  Top 0.254: D48.A 12.06,13.34 10.79,14.61 10.79,20.32 11.43,20.32 D29.A 12.06,20.95 5.71,27.3 5.71,54.61 18.41,54.61 19.68,55.88 A6.E
  Bottom 0.254: A6.E 20.32,56.52 19.05,57.78 19.05,66.67 20.32,67.94 A5.E
TIMING+  (via drill 0.61)
  Top 0.254: D2.A 88.27,71.12 87,71.12 R3.1 85.72,71.12 81.28,75.56 v31.75,75.56
  Bottom 0.254: A2.K 25.4,93.34 26.67,92.08 26.67,83.19 25.4,81.92 A3.K 26.04,81.28 v31.75,75.56
TIMING-
  Top 0.254: D3.A 90.81,71.75 86.36,76.2 36.2,76.2 31.75,80.64 31.75,83.19 30.48,83.19 A3.R
  Bottom 0.254: A2.R 30.48,95.89 31.75,94.61 31.75,85.72 30.48,84.45 A3.R
TIMINGCT
  Top 0.254: IC2.4 97.79,60.96 94.61,60.96 D4.C 93.34,61.59 88.9,66.04 31.11,66.04 29.21,67.94 29.21,80.64 27.94,80.64 A3.M
  Bottom 0.254: A3.M 27.94,81.92 29.21,83.19 29.21,92.08 27.94,93.34 A2.M
TIN
  Top 0.254: IC1.6 104.78,28.57 109.22,33.02 109.22,43.18 128.27,43.18 RN3.8
  Bottom 0.254: IC2.2 98.42,65.41 97.16,64.14 97.16,57.78 97.79,57.15 104.78,57.15 104.78,42.55 106.05,41.27 106.05,29.84 104.78,28.57 IC1.6
TOUT  (via drill 0.61)
  Top 0.254: v95.89,19.05 106.68,19.05 110.49,15.24 IC1.18
  Bottom 0.254: v95.89,19.05 93.34,21.59 93.34,41.27 90.17,44.45 90.17,57.15 87,60.33 87,60.96 R3.2
V+  (via drill 0.61)
  Top 0.508: v106.05,70.48 111.76,70.48 113.67,68.58 C8.1 114.94,68.58 129.54,68.58 131.44,70.48 137.16,70.48 | 137.16,70.48 137.16,71.12 139.06,71.12 R8.2 140.34,71.12 144.15,71.12 146.69,68.58 C9.1 | 137.16,70.48 137.16,66.67 133.99,63.5 133.35,63.5 IC3.3
  Bottom 0.508: v106.05,70.48 99.69,64.14 IC2.3
VCC  (via drill 0.61)
  Top 0.508: IC1.7 102.87,25.4 92.71,25.4 IC4.16 | v111.76,76.83 143.51,76.83 149.22,71.12 R8.1 | 36.83,29.84 31.11,29.84 29.21,27.94 RN2.1 26.67,27.94 10.16,27.94 8.26,29.84 +5V.1 | 36.83,29.84 38.73,27.94 C4.1 | 36.83,29.84 52.07,29.84 53.98,27.94 C5.1 | IC1.20 111.12,20.95 111.12,22.23 IC1.21 | 116.84,22.86 113.03,22.86 IC1.21 | 116.84,22.86 125.73,22.86 128.27,25.4 RN3.1 | 116.84,22.86 116.84,24.77 C7.1 | v52.7,7.62 55.24,5.08 74.93,5.08 RN4.1 | v107.95,22.86 110.49,22.86 IC1.21
  Bottom 0.508: R8.1 149.86,70.48 152.4,67.94 152.4,66.67 C2.+ | IC4.16 90.81,26.04 90.17,26.67 90.17,27.3 C6.1 90.17,28.57 90.17,38.73 91.44,40.01 R12.1 | v111.76,76.83 110.49,75.56 110.49,46.99 107.31,43.81 107.31,28.57 104.78,26.04 IC1.7 105.41,25.4 v107.95,22.86 | C5.1 54.61,27.3 54.61,26.67 55.24,26.04 IC5.16 55.24,24.77 52.7,22.23 v52.7,7.62 | IC6.16 40.01,26.04 39.37,26.67 39.37,27.3 C4.1 | 116.84,20.32 116.84,24.77 C7.1 | 116.84,20.32 116.84,5.08 77.47,5.08 RN4.1 | 116.84,20.32 118.75,20.32 R1.2
VDD  (via drill 0.61)
  Top 0.508: R1.1 120.02,10.16 121.28,10.16 D1.C 122.56,10.79 123.19,10.79 124.46,12.06 C1.1 125.09,12.7 130.81,12.7 v138.43,20.32 | v132.72,28.57 134.62,26.67 v139.06,26.67
  Bottom 0.508: v132.72,28.57 133.99,28.57 J1.4 | v139.06,26.67 138.43,26.04 v138.43,20.32
VSS
  Bottom 0.508: R2.1 127,10.79 130.18,13.97 130.18,22.86 133.35,26.04 133.99,26.04 J1.3 136.53,26.04 137.79,27.3 137.79,32.38 136.53,33.66 J1.6
WE
  Top 0.254: D17.A 41.91,45.72 41.27,45.72 R9.2 40.01,45.72 38.1,45.72 | 38.1,45.72 34.29,45.72 31.75,48.26 D31.A | 38.1,45.72 38.1,55.24 A6.W
  Bottom 0.254: A5.W 38.1,67.94 37.47,67.31 37.47,59.69 36.83,59.05 36.83,57.78 38.1,56.52 A6.W
WE\  (via drill 0.61)
  Top 0.254: v109.86,44.45 109.22,43.81 88.27,43.81 87.63,44.45 55.88,44.45 54.61,45.72 D17.C
  Bottom 0.254: v109.86,44.45 109.22,43.81 109.22,15.24 104.78,10.79 IC1.13

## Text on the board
Top: VRS | DECtape Drive Emulation
Bottom: DECtape Drive Emulation | VRS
